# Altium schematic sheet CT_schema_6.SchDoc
size 469 x 410 mm
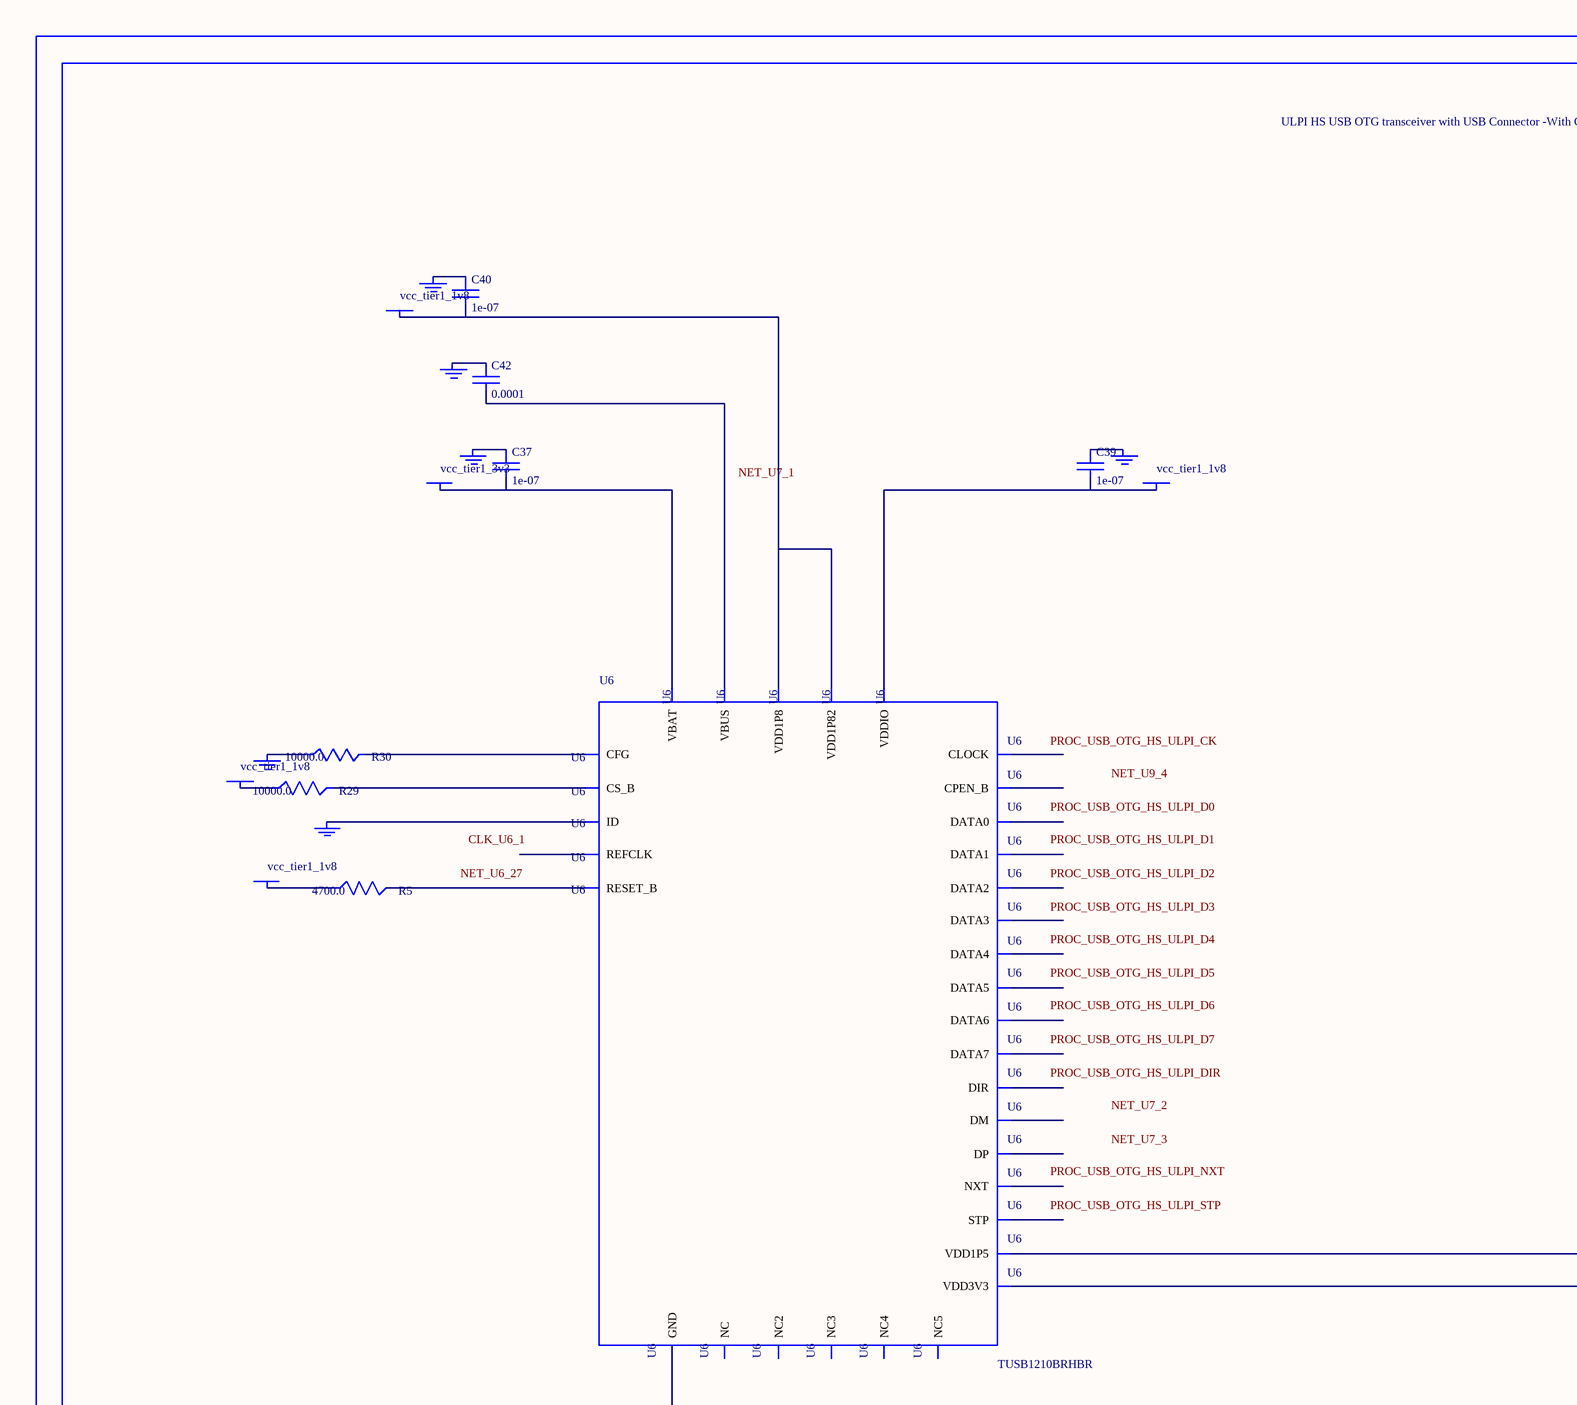
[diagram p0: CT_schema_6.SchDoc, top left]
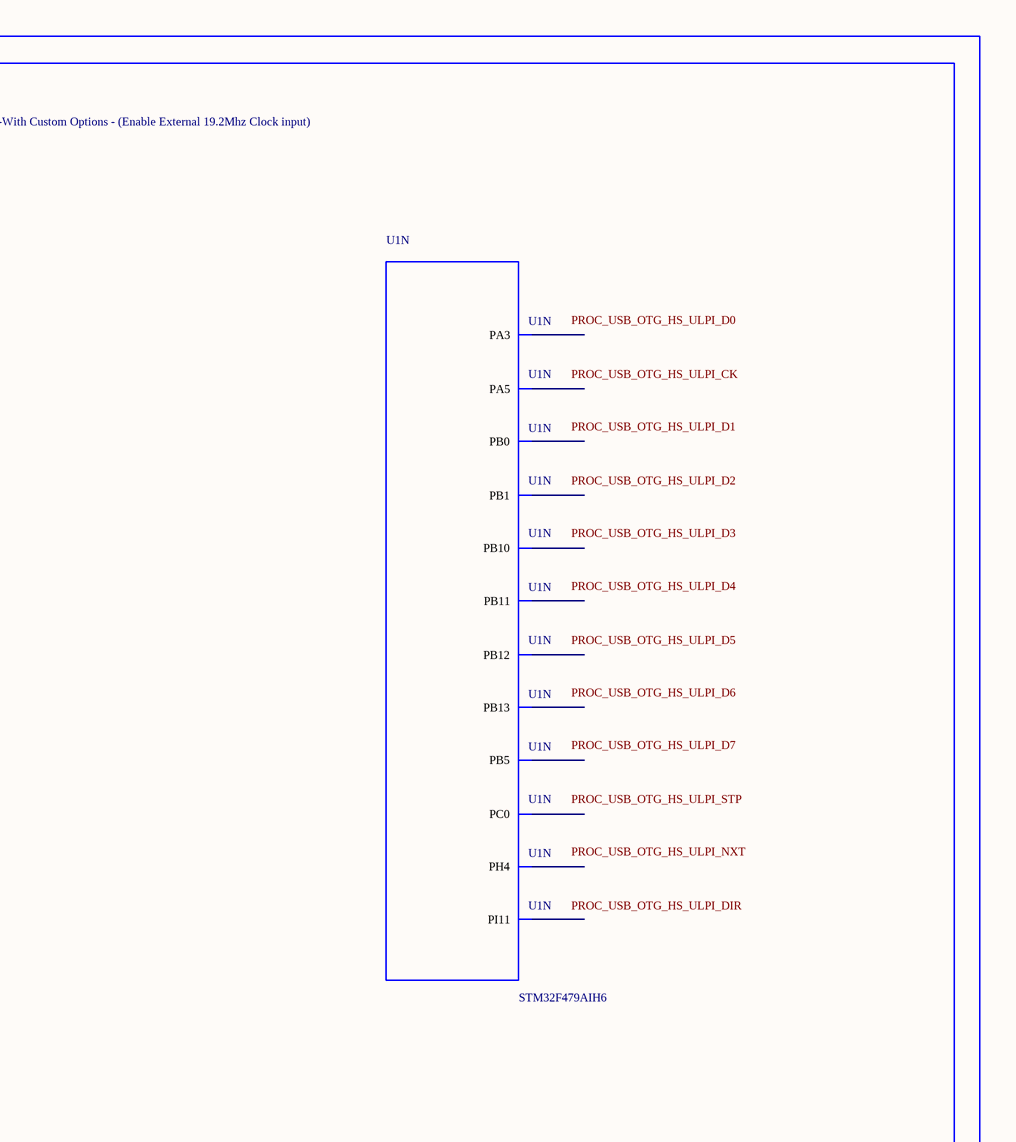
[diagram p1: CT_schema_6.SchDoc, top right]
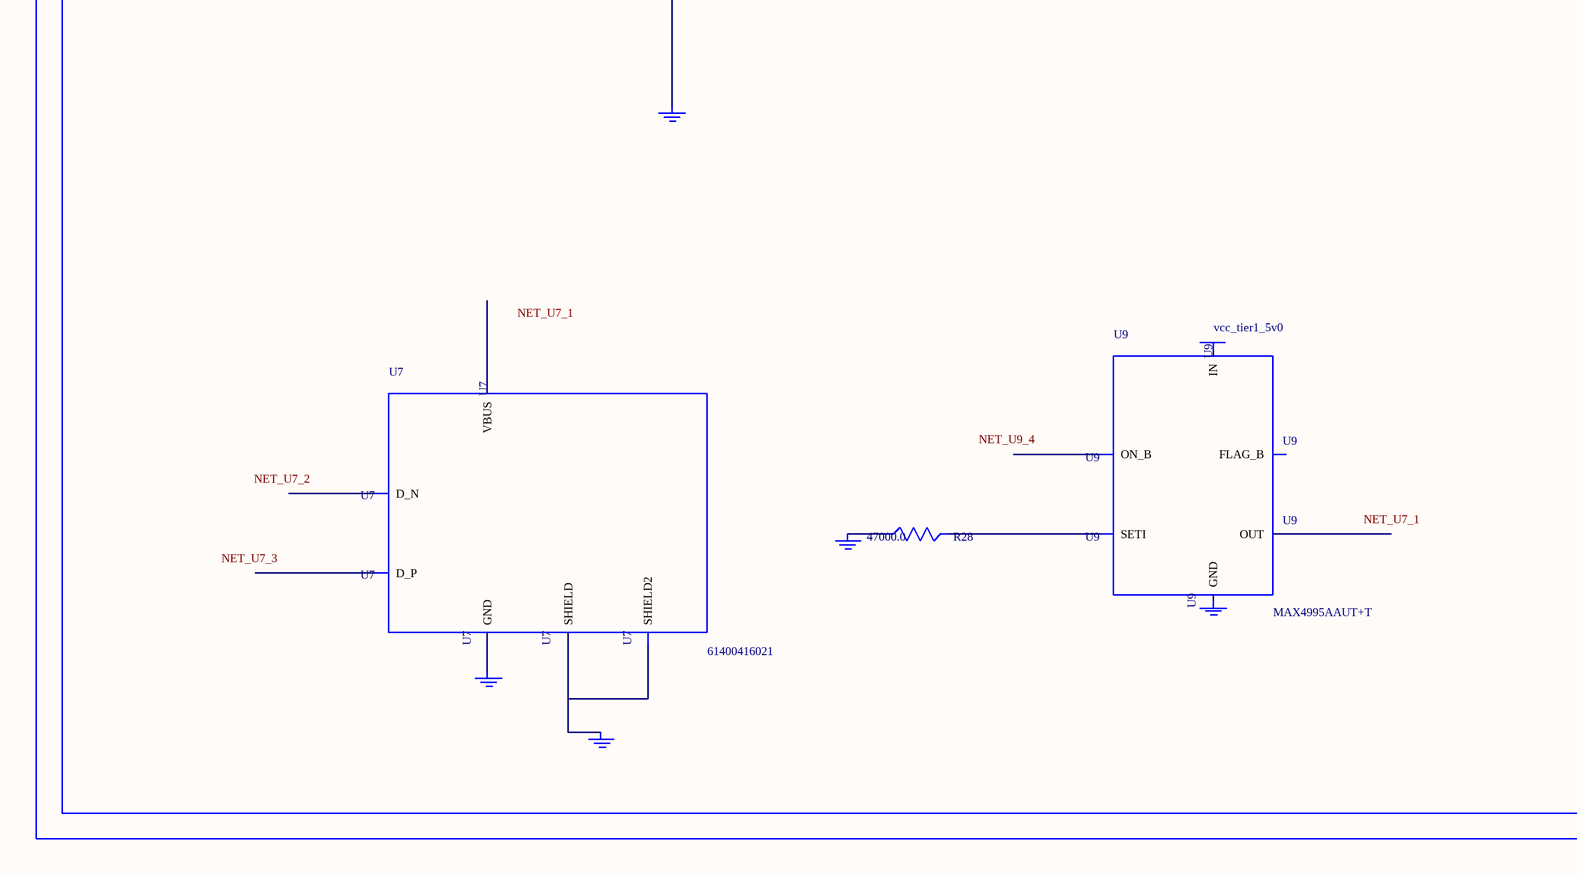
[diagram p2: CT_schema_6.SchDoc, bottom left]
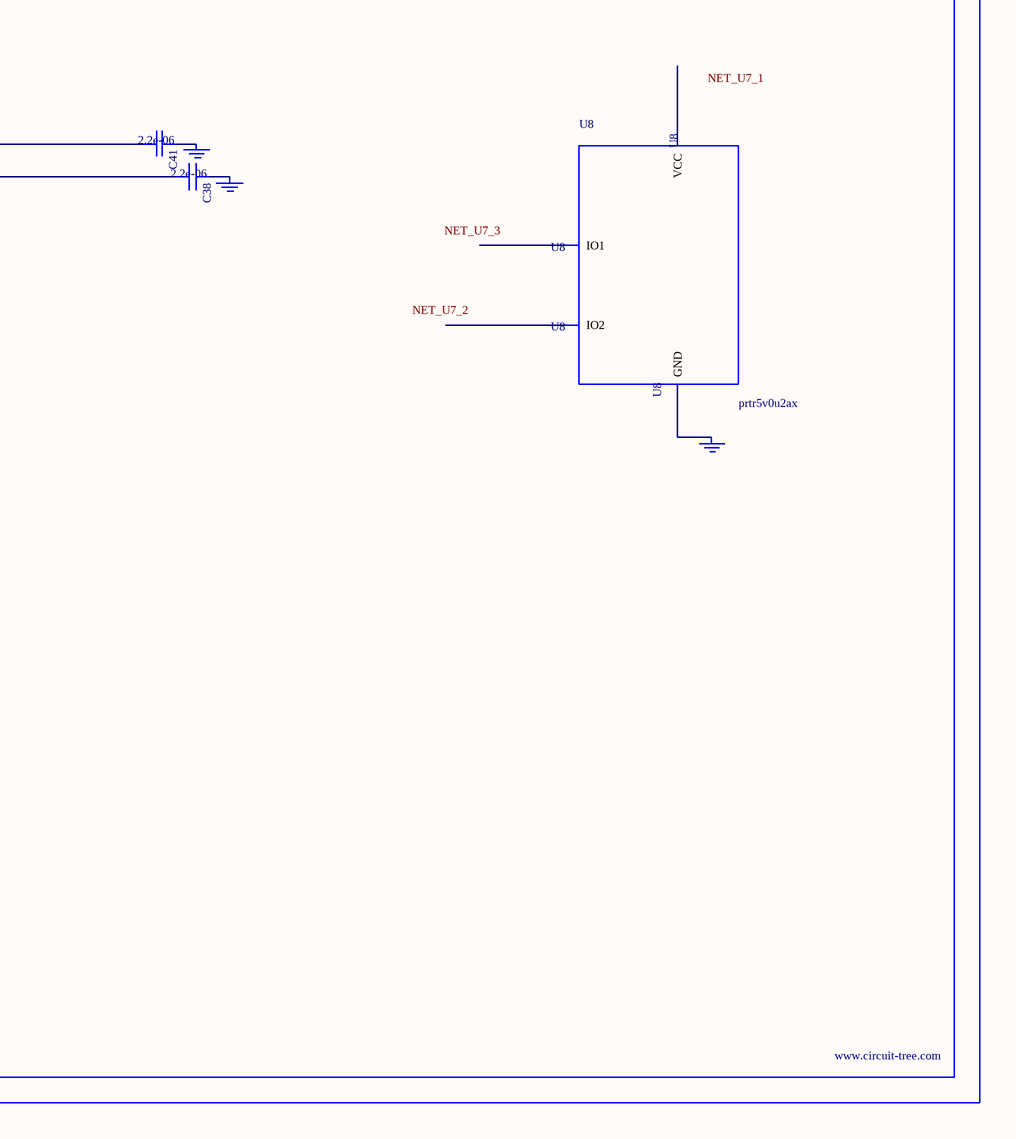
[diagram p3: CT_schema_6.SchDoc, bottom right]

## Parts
BORDER5  (no value)
C37  1e-07  [C0402]
C38  2.2e-06  [C0603]
C39  1e-07  [C0402]
C40  1e-07  [C0402]
C41  2.2e-06  [C0603]
C42  0.0001  [R0603]
GND_INSTANCE_5_0  (no value)
GND_INSTANCE_5_1  (no value)
GND_INSTANCE_5_2  (no value)
GND_INSTANCE_5_3  (no value)
GND_INSTANCE_5_4  (no value)
GND_INSTANCE_5_5  (no value)
GND_INSTANCE_5_6  (no value)
GND_INSTANCE_5_7  (no value)
GND_INSTANCE_5_8  (no value)
GND_INSTANCE_5_9  (no value)
GND_INSTANCE_5_10  (no value)
GND_INSTANCE_5_11  (no value)
GND_INSTANCE_5_12  (no value)
GND_INSTANCE_5_13  (no value)
POWER_INSTANCE_5_0  vcc_tier1_1v8
POWER_INSTANCE_5_1  vcc_tier1_3v3
POWER_INSTANCE_5_2  vcc_tier1_1v8
POWER_INSTANCE_5_3  vcc_tier1_1v8
POWER_INSTANCE_5_4  vcc_tier1_1v8
POWER_INSTANCE_5_5  vcc_tier1_5v0
R5  4700.0  [R0603]
R28  47000.0  [R0603]
R29  10000.0  [R0603]
R30  10000.0  [R0603]
U1  STM32F479AIH6  [UFBGA169]  (part N of 14)
U6  TUSB1210BRHBR  [RHB32_3P45X3P45]
U7  61400416021  [USB-A-H]
U8  prtr5v0u2ax  [SOT143B]
U9  MAX4995AAUT+T  [SOT-23-6]

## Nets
NetC37_1: C37.1 GND_INSTANCE_5_3.0(GND)
NetC37_2: C37.2 POWER_INSTANCE_5_1.0(PWR) U6.21(VBAT)
NetC38_1: C38.1 GND_INSTANCE_5_2.0(GND)
NetC38_2: C38.2 U6.20(VDD3V3)
NetC39_1: C39.1 GND_INSTANCE_5_7.0(GND)
NetC39_2: C39.2 POWER_INSTANCE_5_3.0(PWR) U6.32(VDDIO)
NetC40_1: C40.1 GND_INSTANCE_5_6.0(GND)
NetC40_2: C40.2 POWER_INSTANCE_5_2.0(PWR) U6.28(VDD1P8) U6.30(VDD1P82)
NetC41_1: C41.1 GND_INSTANCE_5_0.0(GND)
NetC41_2: C41.2 U6.12(VDD1P5)
NetC42_1: C42.1 GND_INSTANCE_5_4.0(GND)
NetC42_2: C42.2 U6.22(VBUS)
NetGND_INSTANCE_5_1_0: GND_INSTANCE_5_1.0(GND) R30.1
NetGND_INSTANCE_5_5_0: GND_INSTANCE_5_5.0(GND) U6.23(ID)
NetGND_INSTANCE_5_8_0: GND_INSTANCE_5_8.0(GND) U6.33(GND)
NetGND_INSTANCE_5_9_0: GND_INSTANCE_5_9.0(GND) U7.5(SHIELD) U7.6(SHIELD2)
NetGND_INSTANCE_5_10_0: GND_INSTANCE_5_10.0(GND) U7.4(GND)
NetGND_INSTANCE_5_11_0: GND_INSTANCE_5_11.0(GND) U8.1(GND)
NetGND_INSTANCE_5_12_0: GND_INSTANCE_5_12.0(GND) R28.1
NetPOWER_INSTANCE_5_0_0: POWER_INSTANCE_5_0.0(PWR) R29.1
NetPOWER_INSTANCE_5_4_0: POWER_INSTANCE_5_4.0(PWR) R5.1
NetR5_2: R5.2 U6.27(RESET_B)
NetR28_2: R28.2 U9.3(SETI)
NetR29_2: R29.2 U6.11(CS_B)
NetR30_2: R30.2 U6.14(CFG)

Not connected (* = marked no-connect by the designer): GND_INSTANCE_5_13 0(GND); POWER_INSTANCE_5_5 0(PWR); U1 D5(PB5) F2(PI11) K3(PA3) K5(PB1) M1(PC0) M2(PH4) M3(PA5) M8(PB10) N4(PB0) N8(PB11) N10(PB12) N11(PB13); U6 1(REFCLK) 2(NXT) 3(DATA0) 4(DATA1) 5(DATA2) 6(DATA3) 7(DATA4) 8(NC) 9(DATA5) 10(DATA6) 13(DATA7) 15(NC2) 16(NC3) 17(CPEN_B) 18(DP) 19(DM) 24(NC4) 25(NC5) 26(CLOCK) 29(STP) 31(DIR); U7 1(VBUS) 2(D_N) 3(D_P); U8 2(IO1) 3(IO2) 4(VCC); U9 1(OUT) 2(GND) 4(ON_B) 5(IN) 6(FLAG_B)

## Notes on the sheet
- Labels drawn without touching a wire or pin: CLK_U6_1, NET_U6_27, NET_U7_1, NET_U7_2, NET_U7_3, NET_U9_4, PROC_USB_OTG_HS_ULPI_CK, PROC_USB_OTG_HS_ULPI_D0, PROC_USB_OTG_HS_ULPI_D1, PROC_USB_OTG_HS_ULPI_D2, PROC_USB_OTG_HS_ULPI_D3, PROC_USB_OTG_HS_ULPI_D4, PROC_USB_OTG_HS_ULPI_D5, PROC_USB_OTG_HS_ULPI_D6, PROC_USB_OTG_HS_ULPI_D7, PROC_USB_OTG_HS_ULPI_DIR, PROC_USB_OTG_HS_ULPI_NXT, PROC_USB_OTG_HS_ULPI_STP

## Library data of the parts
BORDER5 = BORDER_PAGE5
C37 C39 C40 = C0402C104K3RACTU
C38 C41 = C0603C225K8RACTU
C42 = C42
GND_INSTANCE_5_0-GND_INSTANCE_5_13 = GND
POWER_INSTANCE_5_0-POWER_INSTANCE_5_5 = PWR
R5 = RC0603JR-074K7L
R28 = RC0603JR-0747KL
R29 R30 = RC0603JR-0710KL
